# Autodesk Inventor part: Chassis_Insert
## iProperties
Created: 2009-02
Part Number: Chassis_Insert
Document SubType Name: Modeling
Designer: claivier
Material: Cuivre
Author: claivier
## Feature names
1. Révolution1 [Revolution]
2. Perçage1 [Hole]
